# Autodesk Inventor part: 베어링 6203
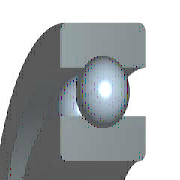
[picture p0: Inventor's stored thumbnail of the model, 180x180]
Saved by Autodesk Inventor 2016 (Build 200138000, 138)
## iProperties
IsCustomPart: 0
Created: 2018-09
Part Number: 베어링 6203
Material: 스테인리스강
Description: 깊은 그루브 볼 베어링
Document SubType Name: Modeling
Standard: KS B 2023
Standards Organization: KS
Language: ko-KR
Size Designation: 6203 - 17 x 40 x 12
Categories: <MemberInstance><Categories><Category DisplayName="샤프트 부품" InternalName="7f7aeb1f-a693-4053-b835-cee3144e0d98" Mnemonic="SHFT"><Category DisplayName="베어링" Inter
Density: 8.08 g/cm^3
Mass: 66.7997 g
Surface Area: 64.3582 cm^2
Volume: 8.26729 cm^3
Appearance: 보라색
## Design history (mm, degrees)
sketch "스케치" dims "d0" = 5.98 (= -0.26 x WD + 0.26 x BD)
  geometry: L1 (3.01, 14.25)-(8.99, 14.25); L2 (6, 14.25)-(6, 11.26); L3 (6, 14.25)-(6, 17.24); L4 (3.778, 12.249)-(0, 12.249); L5 (0, 8.5)-(12, 8.5); L6 (3.778, 16.251)-(0, 16.251); L7 (0, 20)-(12, 20); L8 (12, 8.5)-(12, 12.249); L9 (8.222, 12.249)-(12, 12.249); L10 (8.222, 16.251)-(12, 16.251); L11 (12, 20)-(12, 16.251); L12 (-1.4, 0)-(8.4, 0) reference; L13 (0, -0.3)-(0, 5.3) reference
  constraints: 22 end point, 4 point on line, 2 collinear, 2 perpendicular, 2 symmetric about line, 1 midpoint, 1 parallel, 14 other
  dimensions: "d9" = 17 diameter of L5 L12 (= WD); "d11" = 40 diameter of L7 L12 (= BD); "d12" = 12 distance between parallel lines of L8 L13 (= KB); "d13" = 24.498 diameter of L9 L12 (= 0.326 x BD + 0.674 x WD)
revolve "본체" stored, may be unused: angle "d6" = 90 deg
revolve "볼" stored, may be unused: angle "d7" = 90 deg
pattern_circular "IDS_ARRAYBALL[SIMPL:T]" dims angle "d3" = 360 deg
body "Solid1"
fillet "모깎기1" dims "d1" = 0.6 (= KRS)
other parameters: "WD" = 17 [user parameter; used in 5 equation terms], "BD" = 40 [user parameter; used in 5 equation terms], "KB" = 12 [user parameter; used in 1 equation term], "KRS" = 0.6 [user parameter; used in 1 equation term], "d4" = 0, "d5" = 0, "d8" = 0, "d14" = 0, "d15" = 0, "BBA" = 0 [user parameter], "BC0" = 4750000 [user parameter], "BC" = 9560000 [user parameter], "WR" = 8.5 (= 0.5 x WD) [user parameter]
